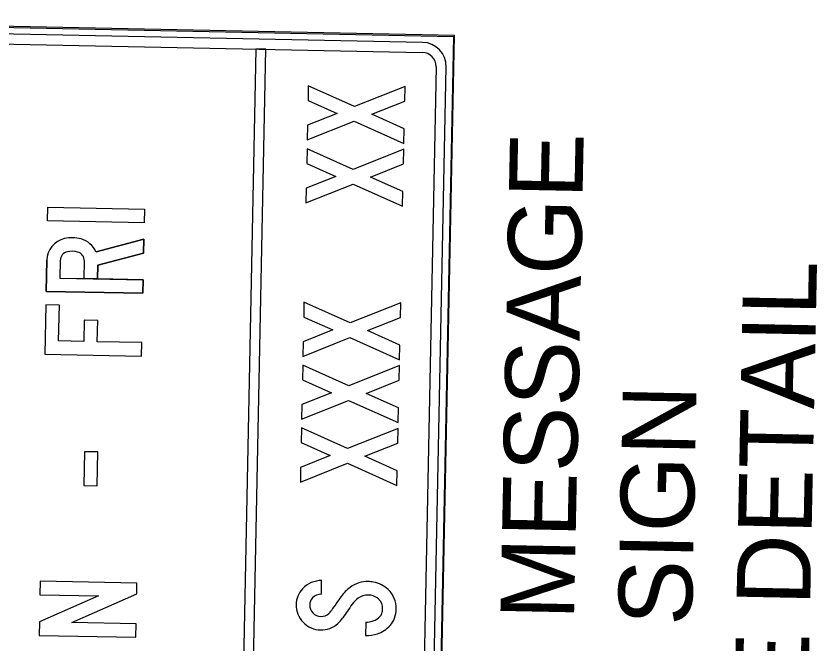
# Model space of a CAD drawing. Extents: x 327762 to 372975, y 127949 to 220470.
# Drawn here: x 354301 to 355660, y 211892 to 212958 of the extents above; entities that cross this region are included whole.
import ezdxf

# ---------------------------------------------------------------- set-up
doc = ezdxf.new("R2010")
doc.units = 0
doc.layers.add('P_MISC_TXT', color=7, linetype='Continuous')
doc.layers.add('P_SGN_Cell', color=7, linetype='Continuous')

msp = doc.modelspace()

# ---------------------------------------------------------------- linework, layer by layer
at = {"layer": 'P_MISC_TXT'}
for p, q in [((355044.6, 212924.5), (353404.2, 212957.5)), ((355044.6, 212924.5), (353404.2, 212957.5)), ((353405.9, 212955.8), (355042.9, 212922.9)), ((354990.6, 212912.8), (353457.8, 212943.6)), ((353457.5, 212926.6), (354990.2, 212895.7)), ((355042.9, 212922.9), (355009.9, 211284.2)), ((355011.6, 211284.1), (355044.6, 212924.5)), ((355011.6, 211284.1), (355044.6, 212924.5)), ((354707.5, 212901.4), (354675.7, 211320.8)), ((354707.5, 212901.4), (354675.7, 211320.8)), ((354707.5, 212901.4), (354675.7, 211320.8)), ((354692.7, 211320.5), (354724.5, 212901.1)), ((354692.7, 211320.5), (354724.5, 212901.1)), ((354692.7, 211320.5), (354724.5, 212901.1)), ((354724.5, 212901.1), (354707.5, 212901.4)), ((354724.5, 212901.1), (354707.5, 212901.4)), ((354724.5, 212901.1), (354707.5, 212901.4)), ((355013.7, 212871.3), (354982.8, 211338.7)), ((354999.9, 211338.4), (355030.7, 212871)), ((354353, 212542.9), (354351.9, 212490.2)), ((354375.9, 212542.4), (354375.9, 212542.4)), ((354416.9, 212541.6), (354416.9, 212541.6)), ((354416.9, 212541.6), (354416.9, 212541.6))]:
    msp.add_line(p, q, dxfattribs=at)
for points in [[(354904.4, 212790.8), (354960.4, 212813.2), (354960.9, 212838.1), (354875.2, 212803.9), (354796.8, 212838.9), (354796.3, 212814), (354845.5, 212792), (354795.5, 212772), (354795, 212747.1), (354874.7, 212779), (354958.9, 212741.3), (354959.4, 212766.3)], [(354904.4, 212790.8), (354960.4, 212813.2), (354960.9, 212838.1), (354875.2, 212803.9), (354796.8, 212838.9), (354796.3, 212814), (354845.5, 212792), (354795.5, 212772), (354795, 212747.1), (354874.7, 212779), (354958.9, 212741.3), (354959.4, 212766.3)], [(354904.4, 212790.8), (354960.4, 212813.2), (354960.9, 212838.1), (354875.2, 212803.9), (354796.8, 212838.9), (354796.3, 212814), (354845.5, 212792), (354795.5, 212772), (354795, 212747.1), (354874.7, 212779), (354958.9, 212741.3), (354959.4, 212766.3)], [(354902.3, 212684.2), (354958.2, 212706.6), (354958.7, 212731.5), (354873.1, 212697.3), (354794.7, 212732.3), (354794.2, 212707.4), (354843.4, 212685.4), (354793.3, 212665.4), (354792.8, 212640.5), (354872.6, 212672.4), (354956.8, 212634.7), (354957.3, 212659.7)], [(354902.3, 212684.2), (354958.2, 212706.6), (354958.7, 212731.5), (354873.1, 212697.3), (354794.7, 212732.3), (354794.2, 212707.4), (354843.4, 212685.4), (354793.3, 212665.4), (354792.8, 212640.5), (354872.6, 212672.4), (354956.8, 212634.7), (354957.3, 212659.7)], [(354902.3, 212684.2), (354958.2, 212706.6), (354958.7, 212731.5), (354873.1, 212697.3), (354794.7, 212732.3), (354794.2, 212707.4), (354843.4, 212685.4), (354793.3, 212665.4), (354792.8, 212640.5), (354872.6, 212672.4), (354956.8, 212634.7), (354957.3, 212659.7)], [(354354.3, 212609.9), (354354.8, 212632.9), (354518.8, 212629.6), (354518.3, 212606.6)], [(354354.3, 212609.9), (354354.8, 212632.9), (354518.8, 212629.6), (354518.3, 212606.6)], [(354354.3, 212609.9), (354354.8, 212632.9), (354518.8, 212629.6), (354518.3, 212606.6)], [(354438.8, 212404.7), (354439.5, 212440.7), (354416.5, 212441.1), (354415.8, 212405.2), (354373.2, 212406.1), (354374.4, 212466.7), (354351.4, 212467.2), (354349.8, 212383.6), (354513.8, 212380.3), (354514.2, 212403.2)], [(354438.8, 212404.7), (354439.5, 212440.7), (354416.5, 212441.1), (354415.8, 212405.2), (354373.2, 212406.1), (354374.4, 212466.7), (354351.4, 212467.2), (354349.8, 212383.6), (354513.8, 212380.3), (354514.2, 212403.2)], [(354438.8, 212404.7), (354439.5, 212440.7), (354416.5, 212441.1), (354415.8, 212405.2), (354373.2, 212406.1), (354374.4, 212466.7), (354351.4, 212467.2), (354349.8, 212383.6), (354513.8, 212380.3), (354514.2, 212403.2)], [(354897, 212423.5), (354953, 212445.8), (354953.5, 212470.7), (354867.8, 212436.5), (354789.4, 212471.6), (354788.9, 212446.6), (354838.1, 212424.7), (354788.1, 212404.7), (354787.6, 212379.7), (354867.3, 212411.6), (354951.5, 212374), (354952, 212398.9)], [(354897, 212423.5), (354953, 212445.8), (354953.5, 212470.7), (354867.8, 212436.5), (354789.4, 212471.6), (354788.9, 212446.6), (354838.1, 212424.7), (354788.1, 212404.7), (354787.6, 212379.7), (354867.3, 212411.6), (354951.5, 212374), (354952, 212398.9)], [(354897, 212423.5), (354953, 212445.8), (354953.5, 212470.7), (354867.8, 212436.5), (354789.4, 212471.6), (354788.9, 212446.6), (354838.1, 212424.7), (354788.1, 212404.7), (354787.6, 212379.7), (354867.3, 212411.6), (354951.5, 212374), (354952, 212398.9)], [(354894.9, 212316.9), (354950.8, 212339.2), (354951.3, 212364.1), (354865.7, 212329.9), (354787.3, 212365), (354786.8, 212340), (354836, 212318.1), (354785.9, 212298.1), (354785.4, 212273.1), (354865.2, 212305), (354949.4, 212267.4), (354949.9, 212292.3)], [(354894.9, 212316.9), (354950.8, 212339.2), (354951.3, 212364.1), (354865.7, 212329.9), (354787.3, 212365), (354786.8, 212340), (354836, 212318.1), (354785.9, 212298.1), (354785.4, 212273.1), (354865.2, 212305), (354949.4, 212267.4), (354949.9, 212292.3)], [(354894.9, 212316.9), (354950.8, 212339.2), (354951.3, 212364.1), (354865.7, 212329.9), (354787.3, 212365), (354786.8, 212340), (354836, 212318.1), (354785.9, 212298.1), (354785.4, 212273.1), (354865.2, 212305), (354949.4, 212267.4), (354949.9, 212292.3)], [(354892.8, 212210.3), (354948.7, 212232.6), (354949.2, 212257.5), (354863.5, 212223.3), (354785.1, 212258.4), (354784.6, 212233.4), (354833.8, 212211.4), (354783.8, 212191.5), (354783.3, 212166.5), (354863, 212198.4), (354947.2, 212160.8), (354947.7, 212185.7)], [(354892.8, 212210.3), (354948.7, 212232.6), (354949.2, 212257.5), (354863.5, 212223.3), (354785.1, 212258.4), (354784.6, 212233.4), (354833.8, 212211.4), (354783.8, 212191.5), (354783.3, 212166.5), (354863, 212198.4), (354947.2, 212160.8), (354947.7, 212185.7)], [(354892.8, 212210.3), (354948.7, 212232.6), (354949.2, 212257.5), (354863.5, 212223.3), (354785.1, 212258.4), (354784.6, 212233.4), (354833.8, 212211.4), (354783.8, 212191.5), (354783.3, 212166.5), (354863, 212198.4), (354947.2, 212160.8), (354947.7, 212185.7)], [(354438.8, 212160.3), (354439.9, 212217.7), (354417, 212218.1), (354415.8, 212160.7)], [(354438.8, 212160.3), (354439.9, 212217.7), (354417, 212218.1), (354415.8, 212160.7)], [(354438.8, 212160.3), (354439.9, 212217.7), (354417, 212218.1), (354415.8, 212160.7)], [(354505.6, 211976.8), (354506, 211994.9), (354342, 211998.2), (354341.5, 211975.2), (354440.6, 211973.2), (354340.6, 211929), (354340.2, 211906.3), (354504.2, 211903), (354504.6, 211926), (354395.6, 211928.2)], [(354505.6, 211976.8), (354506, 211994.9), (354342, 211998.2), (354341.5, 211975.2), (354440.6, 211973.2), (354340.6, 211929), (354340.2, 211906.3), (354504.2, 211903), (354504.6, 211926), (354395.6, 211928.2)], [(354505.6, 211976.8), (354506, 211994.9), (354342, 211998.2), (354341.5, 211975.2), (354440.6, 211973.2), (354340.6, 211929), (354340.2, 211906.3), (354504.2, 211903), (354504.6, 211926), (354395.6, 211928.2)]]:
    msp.add_lwpolyline(points, close=True, dxfattribs=at)
for points in [[(354351.9, 212490.2), (354515.9, 212486.9), (354516.4, 212509.8), (354439.3, 212511.4), (354439.8, 212534.4), (354517.3, 212554.8), (354517.8, 212578.7), (354436.7, 212557.4)], [(354436.7, 212557.4), (354517.8, 212578.7), (354517.3, 212554.8), (354439.8, 212534.4), (354439.3, 212511.4), (354416.3, 212511.9), (354416.9, 212541.6)], [(354436.7, 212557.4), (354517.8, 212578.7), (354517.3, 212554.8), (354439.8, 212534.4), (354439.3, 212511.4), (354416.3, 212511.9), (354416.9, 212541.6)], [(354375.9, 212542.4), (354375.3, 212512.7), (354516.4, 212509.8), (354515.9, 212486.9), (354351.9, 212490.2), (354353, 212542.9)], [(354375.9, 212542.4), (354375.3, 212512.7), (354516.4, 212509.8), (354515.9, 212486.9), (354351.9, 212490.2), (354353, 212542.9)], [(354375.9, 212542.4), (354375.3, 212512.7), (354416.3, 212511.8), (354416.9, 212541.6)], [(354819, 211976.3), (354819.4, 211999.3)], [(354819, 211976.3), (354819.4, 211999.3)], [(354819, 211976.3), (354819.4, 211999.3)], [(354894.3, 211928.8), (354893.8, 211905.9)], [(354894.3, 211928.8), (354893.8, 211905.9)], [(354894.3, 211928.8), (354893.8, 211905.9)]]:
    msp.add_lwpolyline(points, dxfattribs=at)
for radius in [41, 23.9]:
    msp.add_arc((354989.7, 212871.8), radius, 358.8472, 88.8472, dxfattribs=at)
for centre, major_axis, start_param, end_param in [((354396, 212522.1), (-59, 1.2), 4.470023, 4.954755), ((354396, 212522.1), (-59, 1.2), 4.470023, 4.954755), ((354396, 212522.1), (-59, 1.2), 4.470023, 4.954755), ((354391.5, 212542.1), (-38.5, 0.8), 4.954755, 6.283185), ((354391.5, 212542.1), (-38.5, 0.8), 4.954755, 6.283185), ((354391.5, 212542.1), (-38.5, 0.8), 4.954755, 6.283185), ((354401.3, 212541.9), (-38.5, 0.8), 3.574819, 4.470023), ((354401.3, 212541.9), (-38.5, 0.8), 3.574819, 4.470023), ((354401.3, 212541.9), (-38.5, 0.8), 3.574819, 4.470023), ((354391.5, 212542.1), (-15.6, 0.3), 4.954755, 6.283185), ((354391.5, 212542.1), (-15.6, 0.3), 4.954755, 6.283185), ((354391.5, 212542.1), (-15.6, 0.3), 4.954755, 6.283185), ((354396, 212522.1), (-36.1, 0.7), 4.470023, 4.954755), ((354396, 212522.1), (-36.1, 0.7), 4.470023, 4.954755), ((354396, 212522.1), (-36.1, 0.7), 4.470023, 4.954755), ((354401.3, 212541.9), (-15.6, 0.3), 3.141593, 4.470023), ((354401.3, 212541.9), (-15.6, 0.3), 3.141593, 4.470023), ((354401.3, 212541.9), (-15.6, 0.3), 3.141593, 4.470023), ((354818.6, 211956.4), (-42.9, 0.9), 4.712389, 5.561989), ((354818.6, 211956.4), (-42.9, 0.9), 4.712389, 5.561989), ((354818.6, 211956.4), (-42.9, 0.9), 4.712389, 5.561989), ((354897.5, 211947.7), (-50, 1), 4.712389, 5.373599), ((354897.5, 211947.7), (-50, 1), 4.712389, 5.373599), ((354897.5, 211947.7), (-50, 1), 4.712389, 5.373599), ((354897.4, 211943.1), (-54.6, 1.1), 4.552917, 4.712389), ((354897.4, 211943.1), (-54.6, 1.1), 4.552917, 4.712389), ((354897.4, 211943.1), (-54.6, 1.1), 4.552917, 4.712389), ((354898.5, 211948.9), (-48.7, 1), 3.967076, 4.552917), ((354898.5, 211948.9), (-48.7, 1), 3.967076, 4.552917), ((354898.5, 211948.9), (-48.7, 1), 3.967076, 4.552917), ((354817, 211957.8), (-40.8, 0.8), 5.561989, 6.283185), ((354817, 211957.8), (-40.8, 0.8), 5.561989, 6.283185), ((354817, 211957.8), (-40.8, 0.8), 5.561989, 6.283185), ((354909.9, 211931.1), (-70.6, 1.4), 5.373599, 5.679143), ((354909.9, 211931.1), (-70.6, 1.4), 5.373599, 5.679143), ((354909.9, 211931.1), (-70.6, 1.4), 5.373599, 5.679143), ((354901.5, 211952), (-44.4, 0.9), 3.141593, 3.967076), ((354901.5, 211952), (-44.4, 0.9), 3.141593, 3.967076), ((354901.5, 211952), (-44.4, 0.9), 3.141593, 3.967076), ((354817, 211957.8), (-17.9, 0.4), 5.561989, 6.283185), ((354817, 211957.8), (-17.9, 0.4), 5.561989, 6.283185), ((354817, 211957.8), (-17.9, 0.4), 5.561989, 6.283185), ((354818.6, 211956.4), (-19.9, 0.4), 4.712389, 5.561989), ((354818.6, 211956.4), (-19.9, 0.4), 4.712389, 5.561989), ((354818.6, 211956.4), (-19.9, 0.4), 4.712389, 5.561989), ((355636, 211408.2), (-965.3, 19.4), 5.679143, 5.709053), ((355636, 211408.2), (-965.3, 19.4), 5.679143, 5.709053), ((355636, 211408.2), (-965.3, 19.4), 5.679143, 5.709053), ((354909.9, 211931.1), (-47.7, 1), 5.373599, 5.679143), ((354909.9, 211931.1), (-47.7, 1), 5.373599, 5.679143), ((354909.9, 211931.1), (-47.7, 1), 5.373599, 5.679143), ((354897.5, 211947.7), (-27, 0.5), 4.712389, 5.373599), ((354897.5, 211947.7), (-27, 0.5), 4.712389, 5.373599), ((354897.5, 211947.7), (-27, 0.5), 4.712389, 5.373599), ((354897.4, 211943.1), (-31.7, 0.6), 4.552917, 4.712389), ((354897.4, 211943.1), (-31.7, 0.6), 4.552917, 4.712389), ((354897.4, 211943.1), (-31.7, 0.6), 4.552917, 4.712389), ((354898.5, 211948.9), (-25.8, 0.5), 3.967076, 4.552917), ((354898.5, 211948.9), (-25.8, 0.5), 3.967076, 4.552917), ((354898.5, 211948.9), (-25.8, 0.5), 3.967076, 4.552917), ((354818.5, 211957.8), (-42.3, 0.9), 6.283184, 7.853982), ((354818.5, 211957.8), (-42.3, 0.9), 6.283184, 7.853982), ((354818.5, 211957.8), (-42.3, 0.9), 6.283184, 7.853982), ((354818.5, 211957.8), (-19.3, 0.4), 6.283183, 7.853981), ((354818.5, 211957.8), (-19.3, 0.4), 6.283183, 7.853981), ((354818.5, 211957.8), (-19.3, 0.4), 6.283183, 7.853981), ((355636, 211408.2), (-942.3, 19), 5.679143, 5.709053), ((355636, 211408.2), (-942.3, 19), 5.679143, 5.709053), ((355636, 211408.2), (-942.3, 19), 5.679143, 5.709053), ((354901.5, 211952), (-21.4, 0.4), 3.141593, 3.967076), ((354901.5, 211952), (-21.4, 0.4), 3.141593, 3.967076), ((354901.5, 211952), (-21.4, 0.4), 3.141593, 3.967076), ((354818.5, 211957.8), (-19.4, 0.4), 1.570796, 2.321595), ((354818.5, 211957.8), (-19.4, 0.4), 1.570796, 2.321595), ((354818.5, 211957.8), (-19.4, 0.4), 1.570796, 2.321595), ((354812.1, 211964.9), (-28.9, 0.6), 2.321595, 2.56746), ((354812.1, 211964.9), (-28.9, 0.6), 2.321595, 2.56746), ((354812.1, 211964.9), (-28.9, 0.6), 2.321595, 2.56746), ((354906.2, 211949.1), (-16.2, 0.3), 2.431476, 2.811358), ((354906.2, 211949.1), (-16.2, 0.3), 2.431476, 2.811358), ((354906.2, 211949.1), (-16.2, 0.3), 2.431476, 2.811358), ((354897.9, 211952.1), (-25, 0.5), 2.811358, 3.141593), ((354897.9, 211952.1), (-25, 0.5), 2.811358, 3.141593), ((354897.9, 211952.1), (-25, 0.5), 2.811358, 3.141593), ((354897.9, 211952.1), (-48, 1), 2.811358, 3.141593), ((354897.9, 211952.1), (-48, 1), 2.811358, 3.141593), ((354897.9, 211952.1), (-48, 1), 2.811358, 3.141593), ((354812.1, 211964.9), (-51.9, 1), 2.321595, 2.56746), ((354812.1, 211964.9), (-51.9, 1), 2.321595, 2.56746), ((354812.1, 211964.9), (-51.9, 1), 2.321595, 2.56746), ((354895, 211966.4), (-37.5, 0.8), 1.570816, 1.909918), ((354895, 211966.4), (-37.5, 0.8), 1.570816, 1.909918), ((354895, 211966.4), (-37.5, 0.8), 1.570816, 1.909918), ((354898.5, 211955.9), (-26.5, 0.5), 1.909925, 2.431476), ((354898.5, 211955.9), (-26.5, 0.5), 1.909925, 2.431476), ((354898.5, 211955.9), (-26.5, 0.5), 1.909925, 2.431476), ((354906.2, 211949.1), (-39.2, 0.8), 2.431476, 2.811358), ((354906.2, 211949.1), (-39.2, 0.8), 2.431476, 2.811358), ((354906.2, 211949.1), (-39.2, 0.8), 2.431476, 2.811358), ((354818.5, 211957.8), (-42.3, 0.9), 1.570796, 2.321595), ((354818.5, 211957.8), (-42.3, 0.9), 1.570796, 2.321595), ((354818.5, 211957.8), (-42.3, 0.9), 1.570796, 2.321595), ((354898.5, 211955.9), (-49.5, 1), 1.909925, 2.431476), ((354898.5, 211955.9), (-49.5, 1), 1.909925, 2.431476), ((354898.5, 211955.9), (-49.5, 1), 1.909925, 2.431476), ((354895, 211966.4), (-60.5, 1.2), 1.570808, 1.909921), ((354895, 211966.4), (-60.5, 1.2), 1.570808, 1.909921), ((354895, 211966.4), (-60.5, 1.2), 1.570808, 1.909921)]:
    msp.add_ellipse(centre, major_axis=major_axis, ratio=0.999993, start_param=start_param, end_param=end_param, dxfattribs=at)

# ---------------------------------------------------------------- texts
at = {"layer": 'P_SGN_Cell'}
for s, p in [('FIXED MESSAGE', (355236.6, 211393.1)), ('SEE DETAIL', (355640.4, 211575)), ('SIGN', (355447.3, 211921.9))]:
    msp.add_text(s, height=125, rotation=88.8462, dxfattribs=at).set_placement(p)

doc.saveas('drawing.dxf')
